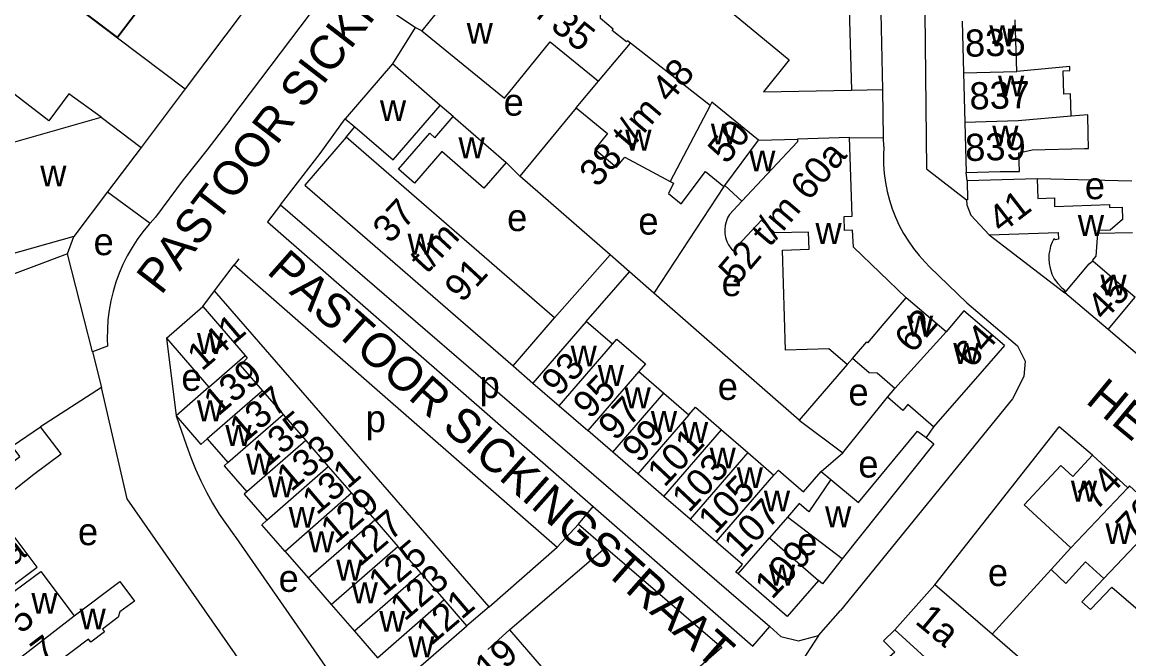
# Model space of a CAD drawing. Extents: x 161141 to 163125, y 381621 to 383200.
# Drawn here: x 161962.7 to 162125.7, y 382135.1 to 382227.5 of the extents above; entities that cross this region are included whole.
import ezdxf

# ---------------------------------------------------------------- set-up
doc = ezdxf.new("R2010")
doc.units = 0
for name, color, linetype in [('BLT_Basislijn', 7, 'Continuous'), ('BLT_Bebouwing', 7, 'Continuous'), ('BLT_Centroide', 7, 'Continuous'), ('BLT_Huisnummer', 7, 'Continuous'), ('BLT_Huisnummer_ tussenligend', 7, 'Continuous'), ('BLT_Huisnummer_reeks', 7, 'Continuous'), ('BLT_Onderdoorgang_en_onderverdeling', 7, 'Continuous'), ('BLT_Onderverdeling_panden', 7, 'Continuous'), ('BLT_Straatnaam', 7, 'Continuous')]:
    doc.layers.add(name, color=color, linetype=linetype)

msp = doc.modelspace()

# ---------------------------------------------------------------- linework, layer by layer
at = {"layer": 'BLT_Basislijn'}
for p, q in [((162084.12, 382245.88), (162084.87, 382217.44)), ((162089.48, 382217.53), (162088.92, 382245.69)), ((161993.47, 382213.21), (162005.18, 382228.73)), ((162020.62, 382226.69), (162017.27, 382221.31)), ((162021.6, 382226.2), (162020.62, 382226.69)), ((161976.79, 382225.15), (161986.74, 382217.64)), ((161986.74, 382217.64), (161980.26, 382208.99)), ((162084.87, 382217.44), (162089.48, 382217.53)), ((162089.62, 382210.44), (162089.48, 382217.53)), ((162026.21, 382213.55), (162024.32, 382215.18)), ((162044.34, 382214.84), (162036.04, 382204.8)), ((162010.44, 382210.51), (162011.73, 382212.03)), ((162084.61, 382210.47), (162089.62, 382210.44)), ((162089.65, 382209.16), (162089.62, 382210.44)), ((162036.04, 382204.8), (162034.01, 382206.79)), ((161986.46, 382204.26), (161982.37, 382198.73)), ((162049.34, 382193.18), (162036.04, 382204.8)), ((162101.91, 382204.07), (162101.79, 382205.3)), ((162126.16, 382204.05), (162112.24, 382204.37)), ((162066.1, 382203.27), (162055.79, 382187.55)), ((161975.29, 382202.45), (161981.57, 382197.86)), ((162000.77, 382200.55), (161998.86, 382198.07)), ((162000.77, 382200.55), (162072.85, 382138.46)), ((161998.86, 382198.07), (162046.82, 382156.12)), ((162105.19, 382196.16), (162116.12, 382187.75)), ((162121.13, 382196.4), (162126.26, 382196.49)), ((161969.41, 382193.32), (161970.32, 382195.91)), ((161969.41, 382193.32), (161958.34, 382189.21)), ((161973.08, 382178.92), (161969.41, 382193.32)), ((162041.15, 382183.89), (162049.34, 382193.18)), ((162052.21, 382190.68), (162049.34, 382193.18)), ((161991.06, 382187.9), (161993.96, 382191.72)), ((161994.62, 382192.58), (161993.96, 382191.72)), ((162045.82, 382183.36), (162052.21, 382190.68)), ((162055.79, 382187.55), (162052.21, 382190.68)), ((161989.34, 382185.57), (161991.06, 382187.9)), ((162031.52, 382141.33), (161991.06, 382187.9)), ((162077.2, 382168.85), (162055.79, 382187.55)), ((161975.3, 382179.75), (161973.08, 382178.92)), ((161973.08, 382178.92), (161974.39, 382173.63)), ((162035.04, 382176.85), (162037.97, 382174.3)), ((162084.25, 382177.05), (162077.2, 382168.85)), ((161974.39, 382173.63), (161965.44, 382167.87)), ((162083.59, 382164), (162090.19, 382172.23)), ((162077.2, 382168.85), (162083.59, 382164)), ((162097.16, 382144.56), (162115.46, 382167.84)), ((162120.4, 382163.66), (162115.46, 382167.84)), ((162080.44, 382161.28), (162083.59, 382164)), ((162044.65, 382153.53), (162046.82, 382156.12)), ((162046.82, 382156.12), (162070.34, 382135.55)), ((162041.55, 382150.1), (162044.65, 382153.53)), ((162044.65, 382153.53), (162048.64, 382150.07)), ((161994.21, 382151.56), (162012.68, 382124.92)), ((162034.5, 382137.93), (162048.64, 382150.07)), ((162048.64, 382150.07), (162065.78, 382135.32)), ((162114.3, 382146.81), (162105.59, 382137.31)), ((162031.52, 382141.33), (162028.24, 382138.55)), ((162034.5, 382137.93), (162031.31, 382135.05)), ((162034.5, 382137.93), (162055.39, 382113.85)), ((162070.34, 382135.55), (162072.85, 382138.46)), ((162080.03, 382137.13), (162077.59, 382133.31))]:
    msp.add_line(p, q, dxfattribs=at)
for points in [[(162095.03, 382288.78), (162095.93, 382205.88), (162101.83, 382201.31)], [(161974.35, 382213.48), (161969.59, 382216.89), (161966.66, 382212.94), (161945.48, 382229.23), (161943.05, 382238.25), (161949.93, 382247.46)], [(162057.12, 382245.71), (162057.51, 382232.36), (162058.97, 382230.53), (162061.47, 382233.7), (162075.73, 382221.94), (162071.94, 382217.2), (162084.87, 382217.44)], [(162020.62, 382226.69), (162017.88, 382228.52), (162027.56, 382241.12), (162025.01, 382243.32)], [(162005.18, 382228.73), (161998.7, 382233.61), (161986.74, 382217.64)], [(161993.47, 382213.21), (161989.93, 382208.62), (161986.67, 382204.52), (161986.46, 382204.26)], [(162000.77, 382200.55), (162006.6, 382208.1), (162010.31, 382213.25)], [(162089.65, 382209.16), (162089.59, 382207.83), (162089.61, 382206.49), (162089.7, 382205.16), (162089.88, 382203.84), (162090.14, 382202.53), (162090.47, 382201.24), (162090.88, 382199.97), (162091.37, 382198.73), (162091.93, 382197.52), (162092.56, 382196.35), (162093.26, 382195.22), (162094.03, 382194.12), (162094.86, 382193.08), (162095.75, 382192.09), (162096.4, 382191.44)], [(161981.57, 382197.86), (161981.41, 382197.69), (161980.51, 382196.6), (161979.68, 382195.46), (161978.91, 382194.27), (161978.21, 382193.04), (161977.57, 382191.78), (161977.02, 382190.48), (161976.53, 382189.15), (161976.12, 382187.79), (161975.79, 382186.42), (161975.54, 382185.03), (161975.36, 382183.62), (161975.27, 382182.21), (161975.25, 382180.8), (161975.3, 382179.75)], [(161982.37, 382198.73), (161981.57, 382197.86)], [(161993.96, 382191.72), (162041.55, 382150.1)], [(162096.4, 382191.44), (162101.88, 382186.14), (162109.34, 382179.77)], [(161983.97, 382180.9), (161985.4, 382169.47)], [(162109.34, 382179.77), (162110.45, 382177.55), (162110.25, 382175.26), (162108.62, 382171.98), (162083.29, 382140.81)], [(162005.5, 382118.08), (161978.19, 382157.25), (161974.39, 382173.63)], [(161985.4, 382169.47), (161986.93, 382165.12), (161987.56, 382163.35), (161988.25, 382161.61), (161989.02, 382159.9), (161989.86, 382158.23), (161990.77, 382156.59), (161991.76, 382155), (161992.8, 382153.45), (161993.92, 382151.94), (161994.21, 382151.56)], [(162096.97, 382167.84), (162095.88, 382166.26)], [(162031.52, 382141.33), (162041.55, 382150.1)], [(162083.51, 382148.41), (162080.63, 382144.72), (162080.02, 382145.23)], [(162080.03, 382137.13), (162083.29, 382140.81)], [(162091.27, 382137.95), (162089.61, 382136.3), (162091.26, 382134.65), (162042.36, 382091.79)], [(162072.85, 382138.46), (162074.48, 382136.95), (162077.06, 382136.34), (162080.03, 382137.13)], [(162065.78, 382135.32), (162059.85, 382130.15), (162065.96, 382123.11)]]:
    msp.add_lwpolyline(points, dxfattribs=at)
at = {"layer": 'BLT_Bebouwing'}
for p, q in [((161967.99, 382231.82), (161976.79, 382225.15)), ((162101.18, 382227.62), (162101.39, 382220.01)), ((162109.23, 382220.2), (162109.01, 382227.8)), ((162021.6, 382226.2), (162033.76, 382216.28)), ((162047.61, 382218.79), (162052.32, 382224.36)), ((162017.27, 382221.31), (162010.31, 382213.25)), ((162024.32, 382215.18), (162017.27, 382221.31)), ((162101.39, 382220.01), (162101.6, 382212.69)), ((162044.34, 382214.84), (162047.61, 382218.79)), ((161974.35, 382213.48), (161980.26, 382208.99)), ((162026.21, 382213.55), (162034.01, 382206.79)), ((162101.6, 382212.69), (162101.79, 382205.3)), ((162071.21, 382210.09), (162076.91, 382210.24)), ((162084.61, 382210.47), (162076.91, 382210.24)), ((161980.26, 382208.99), (161975.29, 382202.45)), ((162066.1, 382203.27), (162066.22, 382203.42)), ((162068.75, 382201.1), (162066.22, 382203.42)), ((161975.29, 382202.45), (161970.32, 382195.91)), ((162122.69, 382182.17), (162116.33, 382187.57)), ((162107.42, 382179.84), (162101.43, 382184.94)), ((162128.65, 382177.11), (162122.69, 382182.17)), ((161983.97, 382180.9), (161990.24, 382173.71)), ((162084.25, 382177.05), (162085.02, 382177.93)), ((162053.55, 382176), (162057.24, 382172.81)), ((161990.24, 382173.71), (161985.4, 382169.47)), ((161998.12, 382173.16), (162001.17, 382169.66)), ((162057.24, 382172.81), (162060.92, 382169.62)), ((162041.83, 382170.96), (162046.03, 382167.32)), ((162001.17, 382169.66), (162004.5, 382165.83)), ((162049.71, 382164.13), (162046.03, 382167.32)), ((162065.76, 382167.42), (162069.61, 382164.08)), ((161989.99, 382166.1), (161993.02, 382162.6)), ((162004.5, 382165.83), (162007.82, 382162.01)), ((162053.4, 382160.94), (162049.71, 382164.13)), ((162069.61, 382164.08), (162073.47, 382160.74)), ((162125.57, 382158.87), (162120.4, 382163.66)), ((162007.82, 382162.01), (162011.26, 382158.06)), ((162057.25, 382157.6), (162053.4, 382160.94)), ((162080.44, 382161.28), (162081.83, 382160.07)), ((162011.26, 382158.06), (162014.67, 382154.14)), ((162061.11, 382154.26), (162057.25, 382157.6)), ((162014.67, 382154.14), (162018.08, 382150.22)), ((162064.96, 382150.92), (162061.11, 382154.26)), ((162075.45, 382154.55), (162072.8, 382151.51)), ((162083.51, 382148.41), (162075.45, 382154.55)), ((162001.45, 382149.51), (162004.85, 382145.6)), ((162021.49, 382146.3), (162018.08, 382150.22)), ((162114.3, 382146.81), (162117.18, 382150.01)), ((162004.85, 382145.6), (162008.26, 382141.68)), ((162024.88, 382142.4), (162021.49, 382146.3)), ((162105.59, 382137.31), (162097.16, 382144.56)), ((162008.26, 382141.68), (162011.67, 382137.76)), ((162113.48, 382130.48), (162105.59, 382137.31))]:
    msp.add_line(p, q, dxfattribs=at)
for points in [[(161968.03, 382231.87), (161976.75, 382225.26), (161987.61, 382239.58), (161978.88, 382246.2)], [(161976.79, 382225.15), (161987.69, 382239.53), (161978.88, 382246.2)], [(162047.74, 382243.97), (162040.37, 382243.89), (162040.38, 382243.6), (162037.57, 382243.56), (162037.56, 382242.35), (162037.38, 382242.31), (162037.38, 382241.05), (162035.67, 382241.02), (162034.59, 382239.68), (162033.43, 382240.61), (162027.51, 382233.42), (162028.26, 382232.81), (162026.55, 382230.75), (162025.8, 382231.36), (162025.4, 382230.86), (162025.59, 382230.7), (162023.85, 382228.57), (162023.66, 382228.73), (162021.6, 382226.2)], [(162052.32, 382224.36), (162051.88, 382224.74), (162051.73, 382224.56), (162049.64, 382226.26), (162049.78, 382226.44), (162047.91, 382228), (162047.81, 382240.67), (162046.88, 382240.67), (162046.82, 382243.35), (162047.75, 382243.36), (162047.74, 382243.97)], [(162033.76, 382216.28), (162040.52, 382224.57), (162047.61, 382218.79)], [(162064.08, 382215.2), (162052.32, 382224.36)], [(162117.23, 382213.6), (162117.16, 382216.91), (162116.16, 382216.88), (162116.08, 382220.31), (162117.07, 382220.36), (162117.05, 382220.95), (162109.23, 382220.2)], [(162071.21, 382210.09), (162064.32, 382215.66), (162064.08, 382215.2)], [(162011.73, 382212.03), (162017.39, 382207.19), (162024.32, 382215.18)], [(162044.34, 382214.84), (162048.93, 382211.05), (162047.07, 382208.76), (162050.27, 382206.11), (162051.48, 382207.59), (162058.18, 382204.01)], [(161970.32, 382195.91), (161960.43, 382193.1), (161956.1, 382208.29), (161974.35, 382213.48)], [(162010.31, 382213.25), (162011.73, 382212.03)], [(162034.01, 382206.79), (162030.74, 382203.02), (162024.52, 382208.4), (162020.51, 382203.77), (162018.18, 382205.79), (162022.77, 382211.1), (162023.52, 382210.45), (162026.21, 382213.55)], [(162101.79, 382205.3), (162106.79, 382205.45), (162109.64, 382205.48), (162109.56, 382208.23), (162111.49, 382208.64), (162119.21, 382208.84), (162119.81, 382208.86), (162119.75, 382211), (162119.68, 382213.82), (162117.23, 382213.6)], [(162010.44, 382210.51), (162004.34, 382203.46), (162035.04, 382176.85)], [(162041.15, 382183.89), (162010.44, 382210.51)], [(162092.93, 382186.86), (162085.18, 382194.32), (162085.05, 382196.84), (162083.88, 382196.77), (162083.8, 382198.85), (162084.99, 382198.88), (162084.61, 382210.47)], [(162058.18, 382204.01), (162058.66, 382203.77), (162057.92, 382202.22), (162059.81, 382200.69), (162063.39, 382205.47), (162066.1, 382203.27)], [(162112.24, 382204.37), (162101.91, 382204.07)], [(162112.24, 382204.37), (162112.32, 382201.49), (162114.77, 382201.57), (162114.81, 382200.33), (162122.89, 382200.6), (162122.9, 382200.17), (162124.74, 382200.23), (162124.8, 382198.41), (162123.01, 382196.85), (162121.16, 382196.8), (162121.13, 382196.4)], [(162101.91, 382204.07), (162101.99, 382201.31), (162101.83, 382201.31)], [(162068.75, 382201.1), (162066.9, 382199.13)], [(162101.83, 382201.31), (162101.86, 382200.54), (162102.49, 382199.06), (162105.19, 382196.16)], [(162066.9, 382199.13), (162066.62, 382198.62), (162066.41, 382198.07), (162066.27, 382197.5), (162066.21, 382196.91), (162066.24, 382196.32), (162066.34, 382195.74), (162066.52, 382195.18), (162066.77, 382194.66), (162067.1, 382194.16), (162067.42, 382193.79)], [(162084.25, 382177.05), (162081.55, 382179.33), (162075.17, 382179.16), (162074.74, 382193.9), (162078.63, 382194.02), (162078.55, 382196.53), (162073.59, 382196.41), (162071.65, 382198.28), (162067.42, 382193.79)], [(162105.19, 382196.16), (162115.35, 382196.47), (162115.39, 382195.51), (162114.89, 382195.39), (162114.71, 382195.54), (162114.47, 382195.07), (162114.22, 382194.47), (162114.09, 382193.86), (162113.98, 382193.31), (162113.94, 382192.67), (162113.99, 382191.92), (162114.13, 382191.21), (162114.41, 382190.34), (162114.73, 382189.66), (162115.26, 382188.96), (162115.87, 382188.35), (162116.31, 382187.99), (162116.12, 382187.75)], [(162121.13, 382196.4), (162120.86, 382192.98), (162120.34, 382192.36), (162120.42, 382192.29)], [(162120.42, 382192.29), (162126.68, 382186.97)], [(162098.81, 382181.86), (162092.93, 382186.86)], [(162116.12, 382187.75), (162116.33, 382187.57)], [(161983.97, 382180.9), (161989.34, 382185.57)], [(161989.34, 382185.57), (161995.56, 382178.36)], [(162101.43, 382184.94), (162098.81, 382181.86)], [(162035.04, 382176.85), (162041.15, 382183.89)], [(162045.82, 382183.36), (162037.97, 382174.3)], [(162049.68, 382180.03), (162045.82, 382183.36)], [(162049.68, 382180.03), (162050.33, 382180.78), (162054.53, 382177.14), (162053.55, 382176)], [(162107.42, 382179.84), (162104.13, 382176.07), (162096.97, 382167.84)], [(161995.56, 382178.36), (161995.89, 382177.99), (161994.82, 382176.96), (161998.12, 382173.16)], [(162091.28, 382173.51), (162088.65, 382175.76), (162087.51, 382175.8), (162085.02, 382177.93)], [(162037.97, 382174.3), (162041.83, 382170.96)], [(162090.19, 382172.23), (162091.28, 382173.51)], [(162096.97, 382167.84), (162093.2, 382171.12), (162092.45, 382170.26), (162090.19, 382172.23)], [(162060.92, 382169.62), (162061.9, 382170.76), (162065.76, 382167.42)], [(161985.4, 382169.47), (161989.04, 382165.27), (161989.99, 382166.1)], [(161951.01, 382158.35), (161955.13, 382161.27), (161956.75, 382159.1), (161962.38, 382163.49), (161961.23, 382165.01), (161965.44, 382167.87)], [(161957.2, 382141.36), (161961.21, 382144.36), (161964.94, 382147.16), (161958.28, 382156.04), (161964.45, 382160.86), (161968.45, 382163.86), (161965.44, 382167.87)], [(162081.83, 382160.07), (162085.9, 382156.7), (162094.61, 382167.23), (162095.88, 382166.26)], [(162095.88, 382166.26), (162097.04, 382165.37), (162083.51, 382148.41)], [(162117.18, 382150.01), (162110.34, 382156.37), (162112.3, 382158.48), (162115.71, 382162.14), (162117.49, 382160.54), (162120.4, 382163.66)], [(161993.02, 382162.6), (161992.46, 382162.11), (161995.81, 382158.26)], [(162073.47, 382160.74), (162074.12, 382161.49), (162077.84, 382158.27)], [(162077.84, 382158.27), (162080.44, 382161.28)], [(162130.73, 382154.65), (162125.83, 382159.15), (162125.57, 382158.87)], [(161995.81, 382158.26), (161995.44, 382157.93), (161998.78, 382154.08)], [(162001.45, 382149.51), (161998.04, 382153.43), (161998.78, 382154.08)], [(162068.17, 382146.18), (162067.84, 382146.46), (162068.81, 382147.59), (162064.96, 382150.92)], [(162072.8, 382151.51), (162080.02, 382145.23)], [(162122.06, 382145.5), (162118.82, 382142.08), (162120.1, 382140.96), (162123.26, 382144.23), (162127.44, 382140.58), (162131.05, 382144.52), (162133.54, 382147.23), (162136.91, 382150.91)], [(162114.3, 382146.81), (162116.48, 382144.79), (162119.37, 382147.94), (162122.06, 382145.5)], [(161957.72, 382140.71), (161961.71, 382143.72), (161965.45, 382146.54), (161970.38, 382139.99)], [(162080.02, 382145.23), (162075.39, 382139.9), (162068.17, 382146.18)], [(161970.38, 382139.99), (161977.09, 382145.05), (161979.25, 382142.19), (161977.11, 382140.58), (161976.88, 382139.8), (161974.54, 382138.04), (161974.84, 382137.64), (161972.83, 382136.12), (161972.5, 382136.55), (161965.08, 382130.95)], [(162097.16, 382144.56), (162091.27, 382137.95)], [(162028.24, 382138.55), (162024.88, 382142.4)], [(162011.67, 382137.76), (162015.08, 382133.84), (162015.46, 382134.17)], [(162018.8, 382130.33), (162028.24, 382138.55)], [(162091.27, 382137.95), (162096.3, 382133.38)]]:
    msp.add_lwpolyline(points, dxfattribs=at)
at = {"layer": 'BLT_Onderdoorgang_en_onderverdeling'}
msp.add_line((162066.22, 382203.42), (162071.21, 382210.09), dxfattribs=at)
msp.add_lwpolyline([(162076.91, 382210.24), (162076.93, 382209.82), (162068.75, 382201.1)], dxfattribs=at)
at = {"layer": 'BLT_Onderverdeling_panden'}
for p, q in [((162101.39, 382220.01), (162109.23, 382220.2)), ((162122.69, 382182.17), (162126.68, 382186.97)), ((162091.28, 382173.51), (162098.81, 382181.86)), ((162041.83, 382170.96), (162049.68, 382180.03)), ((161990.24, 382173.71), (161995.56, 382178.36)), ((162053.55, 382176), (162046.03, 382167.32)), ((161998.12, 382173.16), (161989.99, 382166.1)), ((162049.71, 382164.13), (162057.24, 382172.81)), ((161993.02, 382162.6), (162001.17, 382169.66)), ((162060.92, 382169.62), (162053.4, 382160.94)), ((162057.25, 382157.6), (162065.76, 382167.42)), ((162004.5, 382165.83), (161995.81, 382158.26)), ((162069.61, 382164.08), (162061.11, 382154.26)), ((161998.78, 382154.08), (162007.82, 382162.01)), ((162064.96, 382150.92), (162073.47, 382160.74)), ((162117.18, 382150.01), (162125.57, 382158.87)), ((162011.26, 382158.06), (162001.45, 382149.51)), ((162004.85, 382145.6), (162014.67, 382154.14)), ((162122.06, 382145.5), (162130.73, 382154.65)), ((162068.17, 382146.18), (162072.8, 382151.51)), ((162008.26, 382141.68), (162018.08, 382150.22)), ((162021.49, 382146.3), (162011.67, 382137.76)), ((162015.46, 382134.17), (162024.88, 382142.4)), ((161962.72, 382134.08), (161970.38, 382139.99))]:
    msp.add_line(p, q, dxfattribs=at)
for points in [[(162064.08, 382215.2), (162058.18, 382204.01)], [(162117.23, 382213.6), (162109.44, 382212.91), (162101.6, 382212.69)], [(162116.33, 382187.57), (162119.92, 382191.89), (162120.42, 382192.29)], [(162085.02, 382177.93), (162087.13, 382180.37), (162087.29, 382180.24), (162089.69, 382183.06), (162092.93, 382186.86)], [(162081.83, 382160.07), (162078.62, 382155.31), (162077.19, 382156.56), (162075.45, 382154.55)]]:
    msp.add_lwpolyline(points, dxfattribs=at)

# ---------------------------------------------------------------- texts
at = {"layer": 'BLT_Centroide'}
for s, p in [('w', (162028.2, 382224.29)), ('w', (162105.2, 382223.91)), ('w', (162106.47, 382216.53)), ('w', (162015.42, 382212.89)), ('e', (162033.64, 382213.69)), ('w', (162064.17, 382209.45)), ('w', (162051.56, 382208.54)), ('w', (162105.62, 382209.16)), ('w', (162027, 382207.42)), ('w', (162069.82, 382205.49)), ('w', (161965.39, 382203.28)), ('e', (162119.26, 382201.39)), ('e', (162034.16, 382196.69)), ('e', (162053.49, 382196.17)), ('w', (162079.58, 382194.8)), ('w', (162118.23, 382195.97)), ('e', (161973.24, 382193.14)), ('w', (162019.49, 382193.24)), ('e', (162065.75, 382187.11)), ('w', (162121.55, 382187.22)), ('w', (162093.05, 382181.16)), ('w', (161988.47, 382178.59)), ('w', (162043.51, 382176.76)), ('w', (162099.88, 382177.12)), ('w', (162047.51, 382173.87)), ('e', (161986.18, 382173.16)), ('p', (162030.1, 382172.1)), ('e', (162065.18, 382171.82)), ('w', (162051.45, 382170.6)), ('e', (162084.43, 382170.99)), ('w', (161988.47, 382168.67)), ('p', (162013.33, 382167.07)), ('w', (162055.33, 382167.09)), ('w', (162059.91, 382165.49)), ('w', (161992.65, 382165.03)), ('w', (161995.7, 382160.81)), ('w', (162063.98, 382161.73)), ('e', (162085.89, 382160.38)), ('w', (162067.98, 382158.83)), ('w', (161998.9, 382157.48)), ('w', (162117.2, 382156.84)), ('w', (162071.98, 382155.38)), ('w', (162001.98, 382152.98)), ('w', (162080.99, 382153.07)), ('w', (162122.28, 382150.58)), ('e', (161970.94, 382150.42)), ('w', (162004.86, 382149.38)), ('e', (162076.9, 382148.93)), ('w', (162008.99, 382145.19)), ('w', (162072.72, 382144.47)), ('e', (162104.98, 382144.4)), ('e', (162000.5, 382143.54)), ('w', (162011.26, 382141.86)), ('w', (161964.08, 382140.31)), ('w', (161971.18, 382138)), ('w', (162015.33, 382137.67)), ('w', (162019.58, 382133.91))]:
    msp.add_text(s, height=4, dxfattribs=at).set_placement(p)
at = {"layer": 'BLT_Huisnummer'}
for s, rotation, p in [('50', 50.8612, (162066.48, 382206.4)), ('839', 1.6449, (162101.68, 382206.99)), ('41', 37.661, (162106.97, 382196.23)), ('45', 46.9532, (162122.12, 382183.3)), ('62', 49.5752, (162093.91, 382178.51)), ('141', 40.407, (161989.19, 382175.96)), ('64', 48.966, (162102.65, 382176.3)), ('93', 46.7149, (162041.76, 382172.15)), ('137', 40.407, (161995.39, 382165.32)), ('97', 46.7149, (162050.11, 382165.63)), ('101', 46.7149, (162057.34, 382158.83)), ('133', 40.407, (162002.35, 382158.17)), ('74', 46.5474, (162120.91, 382155.34)), ('105', 46.7149, (162064.82, 382151.87)), ('129', 40.407, (162008.84, 382150.46)), ('125', 40.407, (162015.88, 382142.74)), ('109', 46.7149, (162073.17, 382142.28)), ('121', 40.407, (162022.9, 382135.48)), ('5', 37.0202, (161962.47, 382137.25)), ('1a', 320.5474, (162094.08, 382139)), ('7', 37.0202, (161965.93, 382132.46)), ('119', 41.3344, (162029.36, 382128.13))]:
    msp.add_text(s, height=4, rotation=rotation, dxfattribs=at).set_placement(p)
at = {"layer": 'BLT_Huisnummer_ tussenligend'}
for s, rotation, p in [('835', 1.3742, (162101.64, 382222.36)), ('837', 1.5024, (162102.31, 382214.59)), ('139', 40.407, (161991.59, 382169.32)), ('95', 46.7149, (162046.39, 382168.84)), ('135', 40.407, (161998.74, 382161.72)), ('99', 46.7149, (162053.62, 382162.34)), ('103', 46.7149, (162060.95, 382155.07)), ('131', 40.407, (162006.12, 382154.74)), ('107', 46.7149, (162068.56, 382148.39)), ('76', 46.5474, (162126.37, 382150.88)), ('127', 40.407, (162012.42, 382147.11)), ('123', 40.407, (162019.07, 382139.11))]:
    msp.add_text(s, height=4, rotation=rotation, dxfattribs=at).set_placement(p)
at = {"layer": 'BLT_Huisnummer_reeks'}
for s, rotation, p in [('9 t/m 35', 321.5549, (162029.9, 382234.93)), ('38 t/m 48', 49.4301, (162047.48, 382202.97)), ('52 t/m 60a', 49.5752, (162067.99, 382188.54)), ('37', 47.2119, (162016.92, 382194.7)), ('t/m', 47.2119, (162022.33, 382190.26)), ('91', 47.2119, (162027.52, 382186)), ('3-a', 36.8699, (161957.47, 382144.36))]:
    msp.add_text(s, height=4, rotation=rotation, dxfattribs=at).set_placement(p)
at = {"layer": 'BLT_Straatnaam'}
for s, rotation, p in [('PASTOOR SICKINGSTRAAT', 52.4062, (161983.2, 382187.13)), ('PASTOOR SICKINGSTRAAT', 318.4062, (161998.59, 382190.57)), ('HEEZERWEG', 320.4062, (162119.22, 382171.49))]:
    msp.add_text(s, height=5, rotation=rotation, dxfattribs=at).set_placement(p)

doc.saveas('drawing.dxf')
